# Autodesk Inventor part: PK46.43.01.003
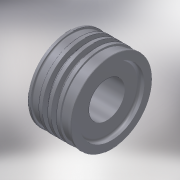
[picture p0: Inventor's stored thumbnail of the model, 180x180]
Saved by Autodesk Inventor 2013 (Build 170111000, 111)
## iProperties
Shininess: 64.0
Length Units: 11269
Angle Units: 11279
Time Units: 11290
Mass Units: 11283
Length Display Precision: 3
Angle Display Precision: 2
Compacted: True
Part Number: PK46.43.01.003
Document SubType Name: Modeling
Created: 2004-11
Material: Сталь высокопрочная низколегированная
Designer: ELarisa
Manufacturer: Standard
Standards Organization: Custom
Density: 7.84 g/cm^3
Density: 0.0
Volumn: 0.0
Area: 0.0
PropertySet Name: Model Information
Control State: 0
Master: False
Checked Out: False
Checked Out Date: 2008-10-15
Last Check In Date: 2008-10-15
Author: ELarisa
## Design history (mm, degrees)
sketch "Эскиз1"
  geometry: L1 (-25, 1.219)-(-25, 50.969); L2 (-25, 50.969)-(-21.5, 50.969); L3 (-21.5, 50.969)-(-21.5, 48.719); L4 (-21.5, 48.719)-(-11.5, 48.719); L5 (-11.5, 48.719)-(-11.5, 50.969); L6 (-11.5, 50.969)-(-7, 50.969); L7 (-7, 50.969)-(-7, 43.469); L8 (-7, 43.469)-(-0.7, 43.469); L9 (-0.7, 43.469)-(-0.7, 50.969); L10 (-0.7, 50.969)-(3.7, 50.969); L11 (3.7, 50.969)-(3.7, 43.469); L12 (10, 43.469)-(10, 50.969); L13 (28, 50.969)-(28, 1.219); L14 (28, 1.219)-(-25, 1.219); L15 (-19, 23.219)-(22, 23.219); L16 (-19, 23.219)-(-25, 24.826); L17 (14.5, 50.969)-(14.5, 48.719); L18 (14.5, 48.719)-(24.5, 48.719); L19 (24.5, 48.719)-(24.5, 50.969); L20 (10, 50.969)-(14.5, 50.969); L21 (24.5, 50.969)-(28, 50.969); L22 (3.7, 43.469)-(10, 43.469); L23 (28, 41.219)-(25, 41.219); L24 (22, 38.219)-(22, 23.219); A1 r 3 centre (25, 38.219) between (25, 41.219) and (22, 38.219)
  constraints: 48 end point, 12 parallel, 10 collinear, 7 perpendicular, 2 point on circle, 2 point on line, 2 tangent, 1 centre point, 1 vertical
  dimensions: "d0" = 53 distance of L13.end L1.start; "d1" = 49.75 distance between parallel lines of L2 L14; "d2" = 47.5 distance between parallel lines of L14 L4; "d3" = 42.25 distance between parallel lines of L14 L8; "d10" = 22 distance between parallel lines of L14 L15; "d11" = 6 horizontal distance of L15.start L16.end; "d12" = 15 deg angle of L15 L16; "d13" = 3.5 distance between parallel lines of L3 L1; "d14" = 10 distance of L3.end L4.end; "d15" = 6.3 distance of L11.end L12.start; "d16" = 6.3 distance of L7.end L8.end; "d17" = 18 distance between parallel lines of L7 L1; "d26" = 28.7 distance between parallel lines of L11 L1; "d27" = 39.5 distance between parallel lines of L17 L1; "d29" = 10 distance of L17.end L18.end; "d30" = 3 radius of A1; "d31" = 40 distance between parallel lines of L14 L23; "d32" = 6 distance between parallel lines of L13 L24
revolve "Вращение1" sketch "Эскиз1" stored, may be unused: angle "d19" = 90 deg
chamfer "Фаска1" distance "d20" = 0.5; stored, may be unused: second distance "d21" = 2, angle "d25" = 45 deg
fillet "Сопряжение1" dims "d22" = 0.2
fillet "Сопряжение3" dims "d24" = 1.2
body "Solid1"
